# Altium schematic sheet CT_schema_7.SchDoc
size 372 x 245 mm
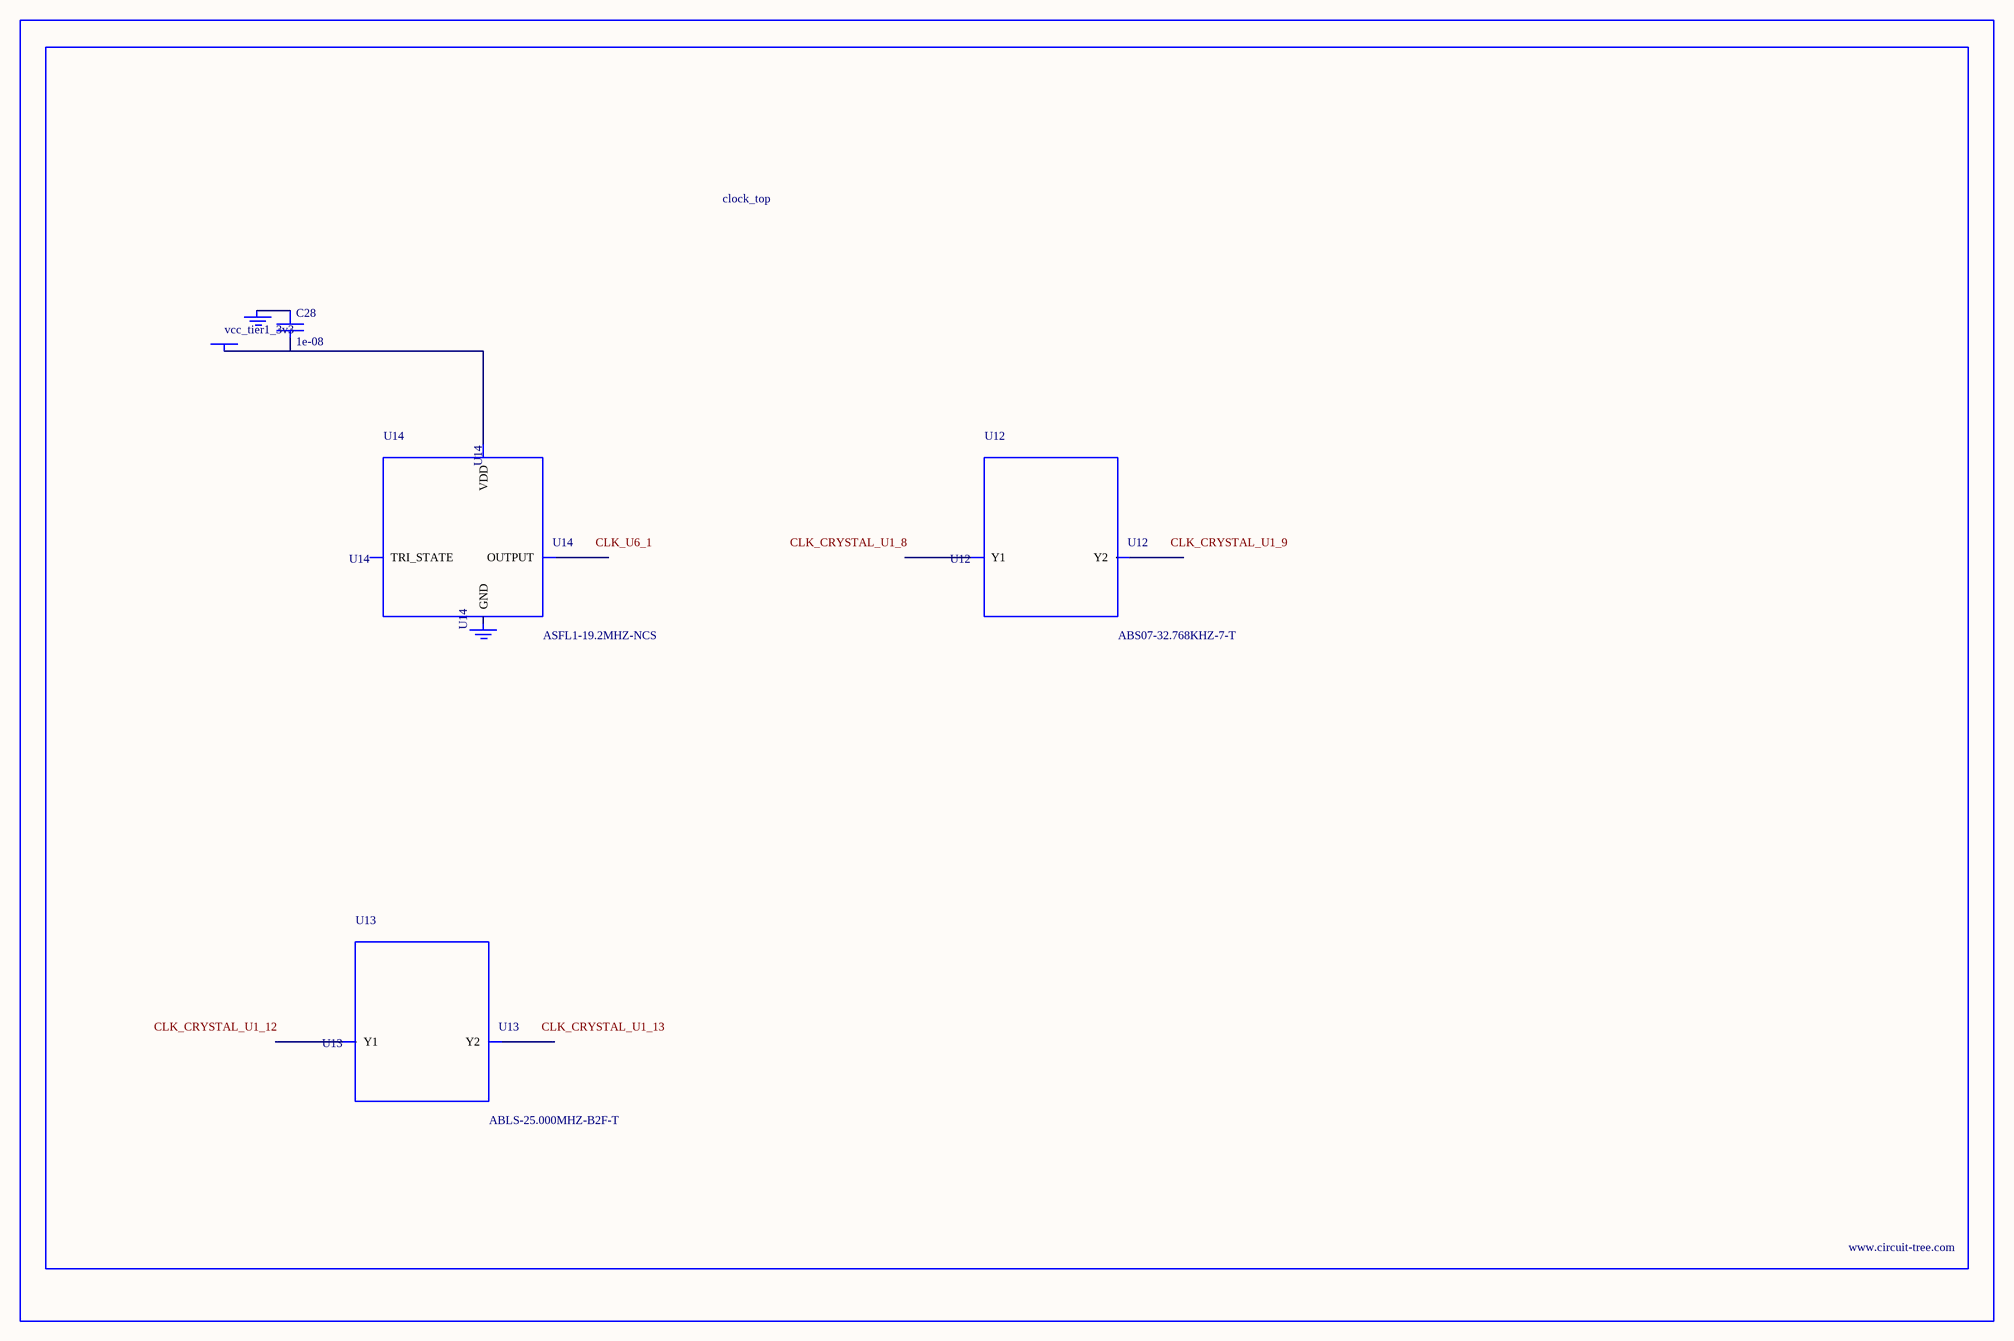
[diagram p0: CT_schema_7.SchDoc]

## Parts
BORDER6  (no value)
C28  1e-08  [C0402]
GND_INSTANCE_6_0  (no value)
GND_INSTANCE_6_1  (no value)
POWER_INSTANCE_6_0  vcc_tier1_3v3
U12  ABS07-32.768KHZ-7-T  [ABS07-32.768KHZ-7-T]
U13  ABLS-25.000MHZ-B2F-T  [ABLS-25.000MHZ-B2F-T]
U14  ASFL1-19.2MHZ-NCS  [ASFL1]

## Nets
NetC28_1: C28.1 GND_INSTANCE_6_0.0(GND)
NetC28_2: C28.2 POWER_INSTANCE_6_0.0(PWR) U14.4(VDD)

Not connected (* = marked no-connect by the designer): GND_INSTANCE_6_1 0(GND); U12 1(Y1) 2(Y2); U13 1(Y1) 2(Y2); U14 1(TRI_STATE) 2(GND) 3(OUTPUT)

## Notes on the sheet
- Labels drawn without touching a wire or pin: CLK_CRYSTAL_U1_8, CLK_CRYSTAL_U1_9, CLK_CRYSTAL_U1_12, CLK_CRYSTAL_U1_13, CLK_U6_1

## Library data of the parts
BORDER6 = BORDER_PAGE6
C28 = C0402C103K3RAC
GND_INSTANCE_6_0 GND_INSTANCE_6_1 = GND
POWER_INSTANCE_6_0 = PWR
